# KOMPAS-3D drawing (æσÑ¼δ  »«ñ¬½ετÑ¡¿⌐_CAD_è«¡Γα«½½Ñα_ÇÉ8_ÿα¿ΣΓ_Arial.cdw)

Views: Вид 1, Спереди, Спереди 2, Проекционный вид 3
Referenced files in D:\Фрагменты для КОМПАС\Элементы для схем\: разъем вилка.frw, разъем гнездо.frw
Referenced files in D:\Рабочая папка\Новое\KSB_Наш_Контроллер\ВЫХОД\КД\11032019_Комплект_КД_с_моделями\КНМБ_424318_050_КД\: Технологическая_сборка_АР8_v2_0.t3d
Referenced files in D:\Рабочая папка\Новое\KSB_Наш_Контроллер\ВЫХОД\КД\11032019_Комплект_КД_с_моделями\КНМБ_424318_050_КД\Эксплуатационная_документация_(ЭД)\: Схемы  подключений_CAD_Контроллер_АР8.cdw
Referenced files in D:\Рабочая папка\Новое\KSB_Наш_Контроллер\ВЫХОД\КД\11032019_Комплект_КД_с_моделями\Исходные данные\KSB\: Board.m3d, SO18.m3d, DD7.a3d, SOT-23.m3d, VT7.a3d, CE050M0220REG-1010.m3d, C16.a3d, 2EDGRС-5.0-03P-14.m3d, XS8.a3d, XS9.a3d, 2EDGRС-5.0-02P-14.m3d, XS5.a3d, XS2.a3d, XS13.a3d, XS12.a3d, 2EDGRС-5.0-04P-14.m3d, XS11.a3d, XS10.a3d, SRU5028.m3d, L2.a3d, EDR101A.m3d, K1.a3d, DS1092-12-N8S.m3d, GB1.a3d, C-TYPE_A.m3d, C18.a3d, C17.a3d, Extruded.m3d, 981821032.a3d, Extruded_1.m3d, 981821168.a3d, C11.a3d, C9.a3d, C5.a3d, Extruded_2.m3d, 981821304.a3d, Extruded_3.m3d, 981821440.a3d, C4.a3d, User_Library-IDC-14MS_Pin_1_____________.m3d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
Referenced files in D:\Рабочая папка\Новое\KSB_Наш_Контроллер\ВЫХОД\КД\11032019_Комплект_КД_с_моделями\Исходные данные\Винты гайки шайбы\: Стойка_11мм_М3.m3d, Шайба_М3_DIN125.m3d, Шайба_гроверная_М3_DIN127.m3d, Винт_М3х6_DIN7985.m3d, Саморез_М2,5х6.m3d
Referenced files in D:\Рабочая папка\Новое\KSB_Наш_Контроллер\ВЫХОД\КД\11032019_Комплект_КД_с_моделями\Исходные данные\Батарейка\: CR1220.m3d
Referenced files in D:\Рабочая папка\Новое\KSB_Наш_Контроллер\ВЫХОД\КД\11032019_Комплект_КД_с_моделями\Исходные данные\OrangePI\: Orange-pi-one-board.m3d, inductance.m3d, MicroUSB-B_Molex_105017-0001.m3d, hdmi.m3d, User Library-RMS-001L-08A0-GY_SignalPin.m3d, User Library-RMS-001L-08A0-GY_MechPin.m3d, User Library-RMS-001L-08A0-GY_LEDpin.m3d, User Library-RMS-001L-08A0-GY_CasePin.m3d, User Library-RMS-001L-08A0-GY_body.m3d, User Library-RMS-001L-08A0-GY.a3d, Allwinner-H3.m3d, PLS-1.m3d, USB_Defaut.m3d, MEM2055-00-190-01-A_revG.m3d, PLD-40.m3d, power-connector.m3d, SAMSUNG.m3d, Pushbutton - dik.m3d, Orange-pi-one.a3d
Referenced files in D:\Рабочая папка\Новое\KSB_Наш_Контроллер\ВЫХОД\КД\11032019_Комплект_КД_с_моделями\Исходные данные\microSD_card\micro-sd-slot-with-sd-card.snapshot.2 (1)\: sd.m3d
Referenced files in D:\Рабочая папка\Новое\KSB_Наш_Контроллер\ВЫХОД\КД\11032019_Комплект_КД_с_моделями\Исходные данные\Корпус\: Корпус_низ.m3d, Корпус_верх.m3d
Referenced files in D:\Рабочая папка\Новое\KSB_Наш_Контроллер\ВЫХОД\КД\11032019_Комплект_КД_с_моделями\Исходные данные\Клеммы\2\: 2EGDK-5.08-02P.m3d
Referenced files in D:\Рабочая папка\Новое\KSB_Наш_Контроллер\ВЫХОД\КД\11032019_Комплект_КД_с_моделями\Исходные данные\Клеммы\3\: 2EGDK-5.08-03P.m3d
Referenced files in D:\Рабочая папка\Новое\KSB_Наш_Контроллер\ВЫХОД\КД\11032019_Комплект_КД_с_моделями\Исходные данные\Клеммы\5\: 2EGDK-5.08-05P.m3d
Referenced files in D:\Рабочая папка\Новое\KSB_Наш_Контроллер\ВЫХОД\КД\11032019_Комплект_КД_с_моделями\Исходные данные\Клеммы\4\: 2EGDK-5.08-04P.m3d
Referenced files in D:\Рабочая папка\Новое\KSB_Наш_Контроллер\ВЫХОД\КД\11032019_Комплект_КД_с_моделями\Исходные данные\Клеммы\9\: 2EGDK-5.08-09P.a3d
Referenced files in D:\Рабочая папка\Новое\KSB_Наш_Контроллер\ВЫХОД\КД\11032019_Комплект_КД_с_моделями\Исходные данные\SMA\: Sma female connector.m3d, Nuts etc_Shayba.m3d, Nuts etc_Grover.m3d, Nuts etc_Gayka.m3d
Referenced files in D:\Рабочая папка\Новое\KSB_Наш_Контроллер\ВЫХОД\КД\11032019_Комплект_КД_с_моделями\Исходные данные\SMA_antena\sma-antenna\: GSM_ANT_RA_SMA.m3d, GSM_ANT_WHIP.m3d, GSM_ANTENNA_900MHZ.a3d
Referenced files in D:\Рабочая папка\Новое\KSB_Наш_Контроллер\ВЫХОД\КД\11032019_Комплект_КД_с_моделями\Исходные данные\Модем_SIM800L\: Модем_SIM800L_V2.0_плата.m3d, CircuitWorks-HEADER 2_54 VERTICAL 5X.m3d, CircuitWorks-HEADER 2_54 VERTICAL 2X.m3d, Модем_SIM800L.a3d
Referenced files in D:\Рабочая папка\Новое\KSB_Наш_Контроллер\ВЫХОД\КД\11032019_Комплект_КД_с_моделями\Исходные данные\Радиомодем433\: Радиомодем433_HC11_HC12.m3d, CircuitWorks-HEADER 2_54 VERTICAL 5X.m3d, Радиомодем433_со_штырьками_сборка.a3d
Referenced files in D:\Рабочая папка\Новое\KSB_Наш_Контроллер\ВЫХОД\КД\11032019_Комплект_КД_с_моделями\Исходные данные\Этикетки\: Этикетка_лицевая.m3d, Маркировка_шильдик.m3d, Маркировка_Верх.m3d, Маркировка_Низ.m3d, Маркировка_ANT.m3d, Маркировка_HDMI_USB2.m3d, Гарантийная_пломба_microSD.m3d, Маркировка_ОТК.m3d
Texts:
  Buhalov
  ESKD1
  POLYLINE_STYLE_0.35_RGB_0_127_0
  Чертеж 1. Расположение клемм и разъемов на контроллере
  LAN
  USB
  RS-232
  GND
  OUT
  NO1
  NO2
  NO3
  NO4
  NO5
  NO6
  NO7
  NC7
  DI1
  DI2
  DI3
  DI4
  DI5
  DI6
  DI7
  DI8
  COM
  NO8
  NC8
  Индикатор питания (Желтый)
  Индикатор работы (Зеленый)
  Разъем антенны
  USB2
  HDMI
  ПЛК АР-8
  (DB9-M)
  GSM
  (SMA-F)
  USB 2.0
  (USB-A)
  RS485-1
  RS485-2
  Замкнут
  после запуска
  контроллера
  DCON
  (micro B)
  (RJ-45)
  Ethernet
  ИП2
  Общий выходов 1,2,3
  Выход 1
  Выход 2
  Выход 3
  Общий выходов 4,5,6
  Выход 4
  Выход 5
  Выход 6
  Выход 7 НО
  Общий выхода 7
  Выход 7 НЗ
  Выход 8 НО
  Общий выхода 8
  Выход 8 НЗ
  ИП1, ИП2 - источники питания
  U1, U2, U3, U4 - источники питания,
  могут быть объеденены
  Питание
  ИП1
  Нагрузка
  ИП - источник питания
  Конт.
  Gill Sans Ultra Bold
  Назначение
  Корпус
  RTS
  CTS
  Назначение контактов разъема DB9M
  Кабель
  К локально-вычислительной сети (ЛВС)
  Устройство
  Rок
  Типовое значение:
  Кабель UTP cat.5e
  монитор
  Сенсорная
  панель
  или другие USB
  устройства
  USB-Ethernet
  адаптер
  USB - Wi-Fi
  модем
  Wi-Fi
  к ЛВС
  Прямое подключ.  или через кабель
  DCON - разъеденитель питания
  антенна
  Граница
  Контроллер АР8
  Схемы  подключений
  Бухалов
  Горбунов
  Якимов
  Андреев
  ООО "НПО"Каскад-ГРУП"
  Без основной надписи.
  Board
  SO18
  DD7
  SOT-23
  VT7
  CE050M0220REG-1010
  XS8
  XS9
  XS5
  XS2
  XS13
  XS12
  XS11
  XS10
  SRU5028
  EDR101A
  DS1092-12-N8S
  GB1
  C-TYPE_A
  Extruded
  User_Library-IDC-14MS_Pin_1_____________
  User_Library-IDC-14MS_Case_IDC-14MS_____________
  IDC-14MS
  XP2
  VT1
  SMB
  VD8
  MiniMELF_SOD-80
  VD3
  DA4
  PLS-3R
  XP1
  PBS-5_(DS-1023_-1x5)
  XS7
  MF-MSMF
  FU5
  FU4
  FU3
  FU2
  DS1040
  SA1
  SIP4(stand)
  TO263-5-1
  DA1
  SO16
  DA2
  DA3
  DD2
  DD3
  DD4
  DD5
  DD6
  Jumper
  SRP1265A
  DD1
  VT3
  Поверхности
  VD2
  L-934GD_G
  VD4
  VD6
  VD9
  VD10
  VD11
  VD12
  VD13
  VD14
  VD15
  VD16
  VD17
  VT2
  VT4
  VT5
  VT6
  VT8
  VT10
  VT11
  VT12
  DRB-9MA
  XP3
  PBS-7_(DS1023-1x7)
  XS4
  PBS-3_(DS-1023_-_1x3)
  XS3
  VD1
  VD7
  PBD-40_(DS1023-2X20)
  XS1
  HF41F
  VD18
  VD19
  VD20
  L-934YD
  VD5
  MF-R135
  FU1
  XS6
  VT9
  Плата KSB rev 2.0
  KSB rev. 2.0
  Стойка М3 11 мм
  Стойка М3 L=11мм
  Батарейка CR1220
  Шайба М3
  Шайба гроверная М3
  Винт М3х6
  Orange-pi-one-board
  inductance
  MicroUSB-B_Molex_105017-0001
  hdmi
  User Library-RMS-001L-08A0-GY_SignalPin
  User Library-RMS-001L-08A0-GY_MechPin
  User Library-RMS-001L-08A0-GY_LEDpin
  User Library-RMS-001L-08A0-GY_CasePin
  User Library-RMS-001L-08A0-GY_body
  User Library-RMS-001L-08A0-GY
  Allwinner-H3
  PLS-1
  MEM2055-00-190-01-A_revG
  PLD-40
  power-connector
  SAMSUNG
  Pushbutton - dik
  Микрокомпьютер Orange Pi One
  Micro SD карта
  Mocro SD карта
  Корпус(основание)
  SANHE 23-66A (основание)
  Корпус(крышка)
  SANHE 23-66A (крышка)
  SMA разъем
  SMA разъем на корпус
  SMA шайба стопорная
  SMA гроверная шайба
  SMA гайка
  Антенна GSM/433МГц
  CircuitWorks-HEADER 2_54 VERTICAL 5X
  CircuitWorks-HEADER 2_54 VERTICAL 2X
  Модем SIM800L V2.0
  Саморез М2,5х6
  Радиомодем 433Мгц
  Этикетка лицевая
  Шильдик
  Маркировка верх
  Маркировка низ
  Маркировка SMA
  Маркировка HDMI_USB2
  Гарантийная пломба
  Этикетка ОТК
  Контроллер АР-8
  КНМБ.424318.050
  Сборочный вид
Dimensions and other numbers on the sheet: 24В; 1; 2; 3; 4; 5; 6; 7; 8; 9; 3G/4G USB; 3G/4G; 1:1; 2EDGRС-5.0-03P-14; 2EDGRС-5.0-02P-14; 2EDGRС-5.0-04P-14; 8SO-EP; 2EDGRС-5.0-09P-14; 2EGDK-5.0-02P; 2EGDK-5.0-03P; 2EGDK-5.08-05P; 2EGDK-5.08-04P; 2EGDK-5.0-09P; 2EGDK-5.0-04P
